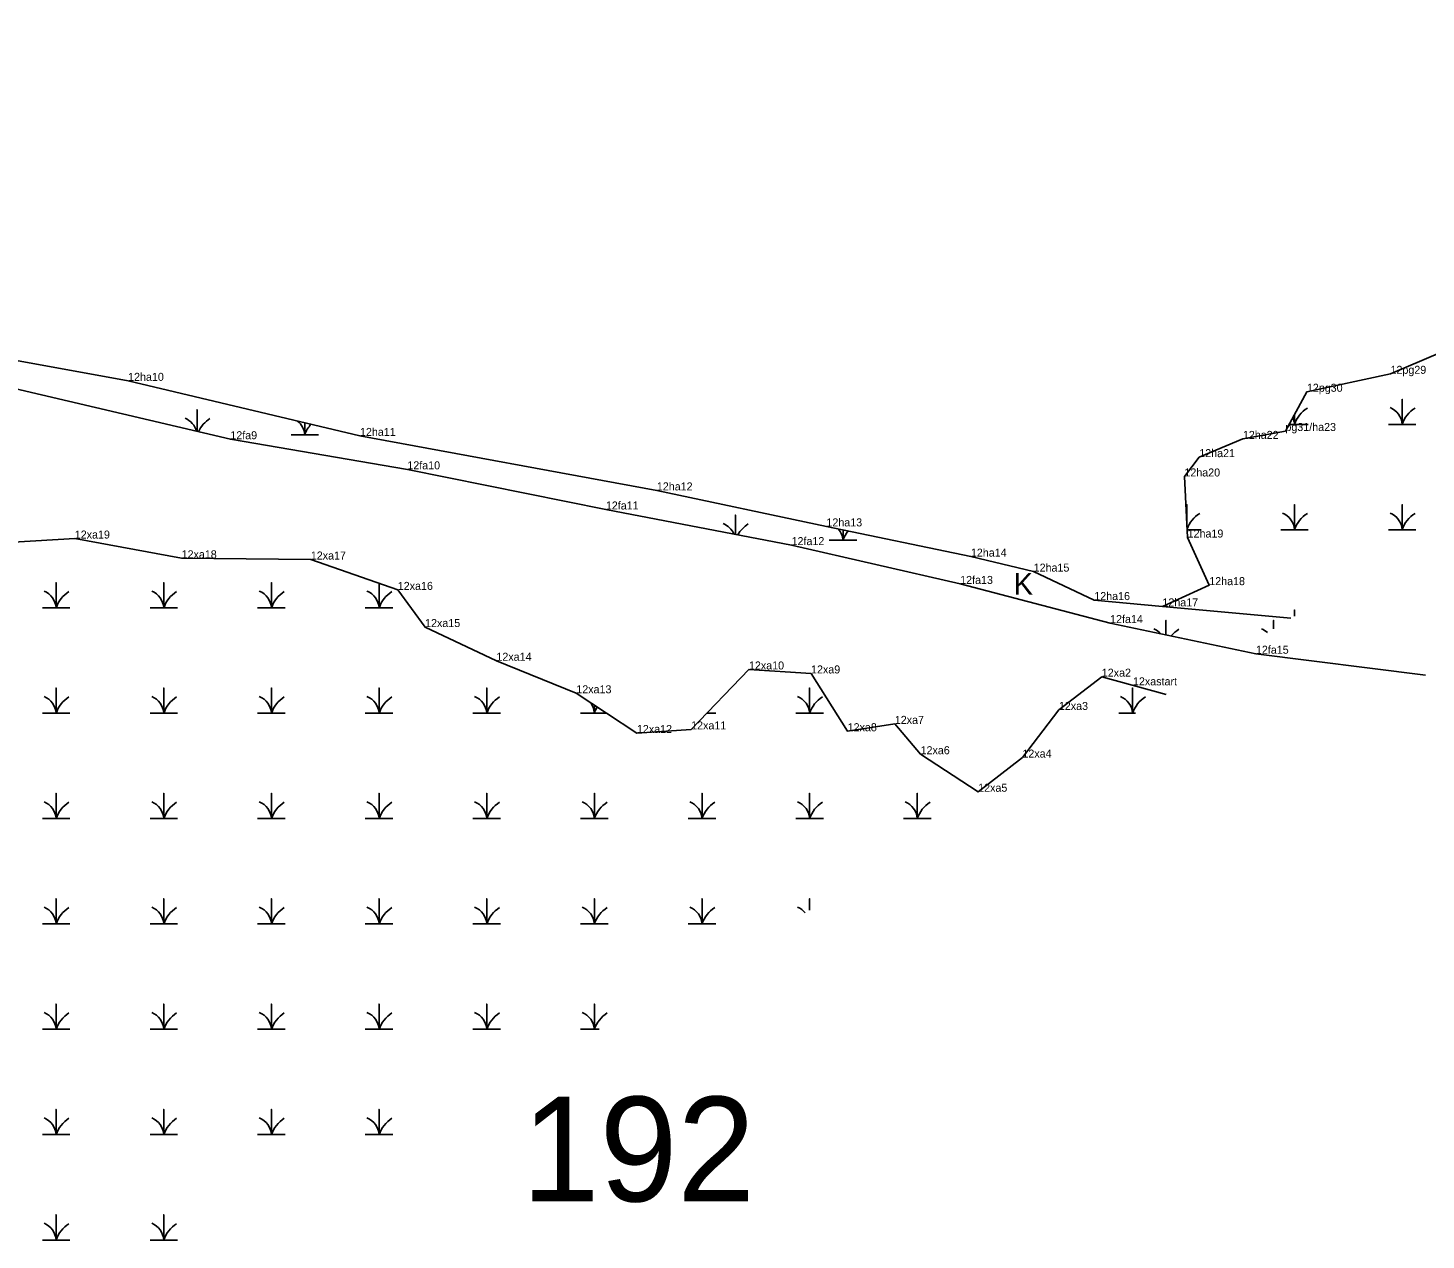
# Model space of a CAD drawing. Extents: x 2072529 to 2268796, y 436423 to 470397.
# Drawn here: x 2227708 to 2228581, y 449868 to 450625 of the extents above; entities that cross this region are included whole.
import ezdxf

# ---------------------------------------------------------------- set-up
doc = ezdxf.new("R2010")
doc.units = 0
for name, color, linetype in [('Default', 7, 'Continuous'), ('Exist Environmental Wetland Boundary', 7, 'Continuous'), ('Exist Environmental Wetland Boundary Cogo Comment', 7, 'Continuous'), ('Exist Environmental Wetland Boundary Cogo Point CELL', 7, 'Continuous'), ('Exist Hydro Swamp or Marsh', 7, 'Continuous')]:
    doc.layers.add(name, color=color, linetype=linetype)

msp = doc.modelspace()

# ---------------------------------------------------------------- linework, layer by layer
at = {"layer": 'Exist Environmental Wetland Boundary'}
msp.add_line((2228416.25, 450264.16), (2228496.47, 450256.71), dxfattribs=at)
for points in [[(2226888, 450625.39), (2226939.13, 450610.14), (2226984.32, 450594.17), (2227058.56, 450564.3), (2227157.52, 450534.56), (2227250.98, 450508.84), (2227383.88, 450477.24), (2227518.96, 450453.03), (2227616.6, 450432.85), (2227770.09, 450405.01), (2227914.95, 450370.61), (2228100.41, 450336.6), (2228206.35, 450314.11), (2228296.59, 450295.23), (2228335.8, 450285.87), (2228373.68, 450268.11), (2228416.25, 450264.16)], [(2228580.63, 450221.11), (2228474.67, 450234.59), (2228383.56, 450253.74), (2228289.9, 450278.18), (2228184.57, 450302.42), (2228068.56, 450324.67), (2227944.54, 450349.74), (2227833.96, 450368.55), (2227682.09, 450404.19), (2227531.66, 450431.23), (2227427.05, 450456.54), (2227285.93, 450486.54), (2227204.01, 450505.24), (2227068.94, 450546.01), (2226965.91, 450582.65), (2226856.88, 450620.93)], [(2228416.25, 450264.16), (2228445.5, 450277.43), (2228432, 450307.16), (2228429.98, 450345.29), (2228439.25, 450357.37), (2228466.52, 450368.75), (2228493.08, 450373.69), (2228506.5, 450398.2), (2228558.73, 450409.4), (2228600.72, 450427.39)], [(2227656.38, 450301.82), (2227736.78, 450306.52), (2227803.52, 450294.18), (2227884.23, 450293.43), (2227938.56, 450274.46), (2227955.62, 450251.26), (2228000.17, 450230.21), (2228050.09, 450209.88), (2228087.95, 450185.09), (2228121.83, 450187.32), (2228157.94, 450224.77), (2228196.73, 450222.29), (2228219.6, 450186.21), (2228249.06, 450190.79), (2228265.17, 450171.83), (2228301.14, 450148.4), (2228328.78, 450169.74), (2228351.55, 450199.49), (2228378.37, 450220.25), (2228418.57, 450209.1)]]:
    msp.add_lwpolyline(points, dxfattribs=at)
at = {"layer": 'Exist Environmental Wetland Boundary Cogo Point CELL'}
for p, q in [((2228558.73, 450409.4), (2228558.73, 450409.4)), ((2227770.09, 450405.01), (2227770.09, 450405.01)), ((2228506.5, 450398.2), (2228506.5, 450398.2)), ((2228493.08, 450373.69), (2228493.08, 450373.69)), ((2227833.96, 450368.55), (2227833.96, 450368.55)), ((2227914.95, 450370.61), (2227914.95, 450370.61)), ((2228466.52, 450368.75), (2228466.52, 450368.75)), ((2228439.25, 450357.37), (2228439.25, 450357.37)), ((2227944.54, 450349.74), (2227944.54, 450349.74)), ((2228429.98, 450345.29), (2228429.98, 450345.29)), ((2228100.41, 450336.6), (2228100.41, 450336.6)), ((2228068.56, 450324.67), (2228068.56, 450324.67)), ((2228206.35, 450314.11), (2228206.35, 450314.11)), ((2227736.78, 450306.52), (2227736.78, 450306.52)), ((2228184.57, 450302.42), (2228184.57, 450302.42)), ((2228432, 450307.16), (2228432, 450307.16)), ((2227803.52, 450294.18), (2227803.52, 450294.18)), ((2227884.23, 450293.43), (2227884.23, 450293.43)), ((2228296.59, 450295.23), (2228296.59, 450295.23)), ((2228335.8, 450285.87), (2228335.8, 450285.87)), ((2228289.9, 450278.18), (2228289.9, 450278.18)), ((2228445.5, 450277.43), (2228445.5, 450277.43)), ((2227938.56, 450274.46), (2227938.56, 450274.46)), ((2228373.68, 450268.11), (2228373.68, 450268.11)), ((2228416.25, 450264.16), (2228416.25, 450264.16)), ((2227955.62, 450251.26), (2227955.62, 450251.26)), ((2228383.56, 450253.74), (2228383.56, 450253.74)), ((2228474.67, 450234.59), (2228474.67, 450234.59)), ((2228000.17, 450230.21), (2228000.17, 450230.21)), ((2228157.94, 450224.77), (2228157.94, 450224.77)), ((2228196.73, 450222.29), (2228196.73, 450222.29)), ((2228378.37, 450220.25), (2228378.37, 450220.25)), ((2228397.85, 450214.84), (2228397.85, 450214.84)), ((2228580.63, 450221.11), (2228580.63, 450221.11)), ((2228050.09, 450209.88), (2228050.09, 450209.88)), ((2228351.55, 450199.49), (2228351.55, 450199.49)), ((2228249.06, 450190.79), (2228249.06, 450190.79)), ((2228087.95, 450185.09), (2228087.95, 450185.09)), ((2228121.83, 450187.32), (2228121.83, 450187.32)), ((2228219.6, 450186.21), (2228219.6, 450186.21)), ((2228265.17, 450171.83), (2228265.17, 450171.83)), ((2228328.78, 450169.74), (2228328.78, 450169.74)), ((2228301.14, 450148.4), (2228301.14, 450148.4))]:
    msp.add_line(p, q, dxfattribs=at)
at = {"layer": 'Exist Hydro Swamp or Marsh'}
for points in [[(2228557.44, 450377.79), (2228566.04, 450377.79), (2228566.04, 450393.57), (2228566.04, 450377.79), (2228574.64, 450377.79)], [(2227813.21, 450373.42), (2227813.21, 450387.01), (2227813.21, 450373.42)], [(2228495.32, 450377.79), (2228498.79, 450377.79), (2228498.79, 450384.12)], [(2228498.79, 450384.12), (2228498.79, 450377.79), (2228507.39, 450377.79)], [(2227871.86, 450371.23), (2227880.46, 450371.23), (2227880.46, 450378.8)], [(2227880.46, 450378.8), (2227880.46, 450371.23), (2227889.07, 450371.23)], [(2228431.54, 450315.86), (2228431.54, 450327.77), (2228431.54, 450315.86)], [(2228490.19, 450311.99), (2228498.79, 450311.99), (2228498.79, 450327.77), (2228498.79, 450311.99), (2228507.39, 450311.99)], [(2228557.44, 450311.99), (2228566.04, 450311.99), (2228566.04, 450327.77), (2228566.04, 450311.99), (2228574.64, 450311.99)], [(2228149.46, 450309.15), (2228149.46, 450321.21), (2228149.46, 450309.15)], [(2228208.11, 450305.43), (2228216.71, 450305.43), (2228216.71, 450311.94)], [(2228216.71, 450311.94), (2228216.71, 450305.43), (2228225.32, 450305.43)], [(2228431.75, 450311.99), (2228440.14, 450311.99)], [(2227716.52, 450263.25), (2227725.12, 450263.25), (2227725.12, 450279.03), (2227725.12, 450263.25), (2227733.72, 450263.25)], [(2227783.77, 450263.25), (2227792.37, 450263.25), (2227792.37, 450279.03), (2227792.37, 450263.25), (2227800.97, 450263.25)], [(2227851.02, 450263.25), (2227859.62, 450263.25), (2227859.62, 450279.03), (2227859.62, 450263.25), (2227868.22, 450263.25)], [(2227918.27, 450263.25), (2227926.87, 450263.25), (2227926.87, 450278.54)], [(2227926.87, 450278.54), (2227926.87, 450263.25), (2227935.47, 450263.25)], [(2228498.79, 450258.12), (2228498.79, 450261.97), (2228498.79, 450258.12)], [(2228418.46, 450246.4), (2228418.46, 450255.41), (2228418.46, 450246.4)], [(2228485.71, 450250.13), (2228485.71, 450255.41), (2228485.71, 450250.13)], [(2227716.52, 450197.45), (2227725.12, 450197.45), (2227725.12, 450213.23), (2227725.12, 450197.45), (2227733.72, 450197.45)], [(2227783.77, 450197.45), (2227792.37, 450197.45), (2227792.37, 450213.23), (2227792.37, 450197.45), (2227800.97, 450197.45)], [(2227851.02, 450197.45), (2227859.62, 450197.45), (2227859.62, 450213.23), (2227859.62, 450197.45), (2227868.22, 450197.45)], [(2227918.27, 450197.45), (2227926.87, 450197.45), (2227926.87, 450213.23), (2227926.87, 450197.45), (2227935.47, 450197.45)], [(2227985.52, 450197.45), (2227994.12, 450197.45), (2227994.12, 450213.23), (2227994.12, 450197.45), (2228002.72, 450197.45)], [(2228187.27, 450197.45), (2228195.87, 450197.45), (2228195.87, 450213.23), (2228195.87, 450197.45), (2228204.47, 450197.45)], [(2228389.02, 450197.45), (2228397.62, 450197.45), (2228397.62, 450213.23), (2228397.62, 450197.45), (2228399.5, 450197.45)], [(2228052.77, 450197.45), (2228061.37, 450197.45), (2228061.37, 450202.49)], [(2228061.37, 450202.49), (2228061.37, 450197.45), (2228069.07, 450197.45)], [(2228131.6, 450197.45), (2228137.22, 450197.45)], [(2227716.52, 450131.65), (2227725.12, 450131.65), (2227725.12, 450147.43), (2227725.12, 450131.65), (2227733.72, 450131.65)], [(2227783.77, 450131.65), (2227792.37, 450131.65), (2227792.37, 450147.43), (2227792.37, 450131.65), (2227800.97, 450131.65)], [(2227851.02, 450131.65), (2227859.62, 450131.65), (2227859.62, 450147.43), (2227859.62, 450131.65), (2227868.22, 450131.65)], [(2227918.27, 450131.65), (2227926.87, 450131.65), (2227926.87, 450147.43), (2227926.87, 450131.65), (2227935.47, 450131.65)], [(2227985.52, 450131.65), (2227994.12, 450131.65), (2227994.12, 450147.43), (2227994.12, 450131.65), (2228002.72, 450131.65)], [(2228052.77, 450131.65), (2228061.37, 450131.65), (2228061.37, 450147.43), (2228061.37, 450131.65), (2228069.97, 450131.65)], [(2228120.02, 450131.65), (2228128.62, 450131.65), (2228128.62, 450147.43), (2228128.62, 450131.65), (2228137.22, 450131.65)], [(2228187.27, 450131.65), (2228195.87, 450131.65), (2228195.87, 450147.43), (2228195.87, 450131.65), (2228204.47, 450131.65)], [(2228254.52, 450131.65), (2228263.12, 450131.65), (2228263.12, 450147.43), (2228263.12, 450131.65), (2228271.72, 450131.65)], [(2227716.52, 450065.85), (2227725.12, 450065.85), (2227725.12, 450081.63), (2227725.12, 450065.85), (2227733.72, 450065.85)], [(2227783.77, 450065.85), (2227792.37, 450065.85), (2227792.37, 450081.63), (2227792.37, 450065.85), (2227800.97, 450065.85)], [(2227851.02, 450065.85), (2227859.62, 450065.85), (2227859.62, 450081.63), (2227859.62, 450065.85), (2227868.22, 450065.85)], [(2227918.27, 450065.85), (2227926.87, 450065.85), (2227926.87, 450081.63), (2227926.87, 450065.85), (2227935.47, 450065.85)], [(2227985.52, 450065.85), (2227994.12, 450065.85), (2227994.12, 450081.63), (2227994.12, 450065.85), (2228002.72, 450065.85)], [(2228052.77, 450065.85), (2228061.37, 450065.85), (2228061.37, 450081.63), (2228061.37, 450065.85), (2228069.97, 450065.85)], [(2228120.02, 450065.85), (2228128.62, 450065.85), (2228128.62, 450081.63), (2228128.62, 450065.85), (2228137.22, 450065.85)], [(2228195.87, 450074.42), (2228195.87, 450081.63), (2228195.87, 450074.42)], [(2227716.52, 450000.05), (2227725.12, 450000.05), (2227725.12, 450015.83), (2227725.12, 450000.05), (2227733.72, 450000.05)], [(2227783.77, 450000.05), (2227792.37, 450000.05), (2227792.37, 450015.83), (2227792.37, 450000.05), (2227800.97, 450000.05)], [(2227851.02, 450000.05), (2227859.62, 450000.05), (2227859.62, 450015.83), (2227859.62, 450000.05), (2227868.22, 450000.05)], [(2227918.27, 450000.05), (2227926.87, 450000.05), (2227926.87, 450015.83), (2227926.87, 450000.05), (2227935.47, 450000.05)], [(2227985.52, 450000.05), (2227994.12, 450000.05), (2227994.12, 450015.83), (2227994.12, 450000.05), (2228002.72, 450000.05)], [(2228052.77, 450000.05), (2228061.37, 450000.05), (2228061.37, 450015.83), (2228061.37, 450000.05), (2228064.46, 450000.05)], [(2227716.52, 449934.25), (2227725.12, 449934.25), (2227725.12, 449950.03), (2227725.12, 449934.25), (2227733.72, 449934.25)], [(2227783.77, 449934.25), (2227792.37, 449934.25), (2227792.37, 449950.03), (2227792.37, 449934.25), (2227800.97, 449934.25)], [(2227851.02, 449934.25), (2227859.62, 449934.25), (2227859.62, 449950.03), (2227859.62, 449934.25), (2227868.22, 449934.25)], [(2227918.27, 449934.25), (2227926.87, 449934.25), (2227926.87, 449950.03), (2227926.87, 449934.25), (2227935.47, 449934.25)], [(2227716.52, 449868.45), (2227725.12, 449868.45), (2227725.12, 449884.23), (2227725.12, 449868.45), (2227733.72, 449868.45)], [(2227783.77, 449868.45), (2227792.37, 449868.45), (2227792.37, 449884.23), (2227792.37, 449868.45), (2227800.97, 449868.45)]]:
    msp.add_lwpolyline(points, dxfattribs=at)
for centre, radius, start, end in [((2227800.95, 450370.34), 12.3, 14.93161, 67.53497), ((2227831.46, 450365.17), 19.22, 122.12745, 155.19214), ((2228486.52, 450376.9), 12.3, 4.14034, 24.93697), ((2228517.03, 450371.73), 19.22, 122.12745, 161.62219), ((2228553.77, 450376.9), 12.3, 4.14034, 67.53497), ((2228584.28, 450371.73), 19.22, 122.12745, 161.62219), ((2227868.2, 450370.34), 12.3, 4.14034, 50.81137), ((2227898.71, 450365.17), 19.22, 138.54347, 161.62219), ((2228449.78, 450305.93), 19.22, 122.12745, 160.0063), ((2228486.52, 450311.1), 12.3, 4.14034, 67.53497), ((2228517.03, 450305.93), 19.22, 122.12745, 161.62219), ((2228553.77, 450311.1), 12.3, 4.14034, 67.53497), ((2228584.28, 450305.93), 19.22, 122.12745, 161.62219), ((2228137.2, 450304.54), 12.3, 22.93407, 67.53497), ((2228167.71, 450299.37), 19.22, 122.12745, 150.41007), ((2228204.45, 450304.54), 12.3, 4.14034, 40.686), ((2228234.96, 450299.37), 19.22, 141.69727, 161.62219), ((2227712.86, 450262.36), 12.3, 4.14034, 67.53497), ((2227743.36, 450257.19), 19.22, 122.12745, 161.62219), ((2227780.11, 450262.36), 12.3, 4.14034, 67.53497), ((2227810.61, 450257.19), 19.22, 122.12745, 161.62219), ((2227847.36, 450262.36), 12.3, 4.14034, 67.53497), ((2227877.86, 450257.19), 19.22, 122.12745, 161.62219), ((2227914.61, 450262.36), 12.3, 4.14034, 67.53497), ((2227945.11, 450257.19), 19.22, 122.12745, 161.62219), ((2228406.2, 450238.74), 12.3, 42.71799, 67.53497), ((2228436.71, 450233.57), 19.22, 122.12745, 140.85091), ((2228473.45, 450238.74), 12.3, 47.11509, 67.53497), ((2227712.86, 450196.56), 12.3, 4.14034, 67.53497), ((2227743.36, 450191.39), 19.22, 122.12745, 161.62219), ((2227780.11, 450196.56), 12.3, 4.14034, 67.53497), ((2227810.61, 450191.39), 19.22, 122.12745, 161.62219), ((2227847.36, 450196.56), 12.3, 4.14034, 67.53497), ((2227877.86, 450191.39), 19.22, 122.12745, 161.62219), ((2227914.61, 450196.56), 12.3, 4.14034, 67.53497), ((2227945.11, 450191.39), 19.22, 122.12745, 161.62219), ((2227981.86, 450196.56), 12.3, 4.14034, 67.53497), ((2228012.36, 450191.39), 19.22, 122.12745, 161.62219), ((2228183.61, 450196.56), 12.3, 4.14034, 67.53497), ((2228214.11, 450191.39), 19.22, 122.12745, 161.62219), ((2228385.36, 450196.56), 12.3, 4.14034, 67.53497), ((2228415.86, 450191.39), 19.22, 122.12745, 161.62219), ((2228049.11, 450196.56), 12.3, 4.14034, 38.52627), ((2228079.61, 450191.39), 19.22, 148.88911, 161.62219), ((2227712.86, 450130.76), 12.3, 4.14034, 67.53497), ((2227743.36, 450125.59), 19.22, 122.12745, 161.62219), ((2227780.11, 450130.76), 12.3, 4.14034, 67.53497), ((2227810.61, 450125.59), 19.22, 122.12745, 161.62219), ((2227847.36, 450130.76), 12.3, 4.14034, 67.53497), ((2227877.86, 450125.59), 19.22, 122.12745, 161.62219), ((2227914.61, 450130.76), 12.3, 4.14034, 67.53497), ((2227945.11, 450125.59), 19.22, 122.12745, 161.62219), ((2227981.86, 450130.76), 12.3, 4.14034, 67.53497), ((2228012.36, 450125.59), 19.22, 122.12745, 161.62219), ((2228049.11, 450130.76), 12.3, 4.14034, 67.53497), ((2228079.61, 450125.59), 19.22, 122.12745, 161.62219), ((2228116.36, 450130.76), 12.3, 4.14034, 67.53497), ((2228146.86, 450125.59), 19.22, 122.12745, 161.62219), ((2228183.61, 450130.76), 12.3, 4.14034, 67.53497), ((2228214.11, 450125.59), 19.22, 122.12745, 161.62219), ((2228250.86, 450130.76), 12.3, 4.14034, 67.53497), ((2228281.36, 450125.59), 19.22, 122.12745, 161.62219), ((2227712.86, 450064.96), 12.3, 4.14034, 67.53497), ((2227743.36, 450059.79), 19.22, 122.12745, 161.62219), ((2227780.11, 450064.96), 12.3, 4.14034, 67.53497), ((2227810.61, 450059.79), 19.22, 122.12745, 161.62219), ((2227847.36, 450064.96), 12.3, 4.14034, 67.53497), ((2227877.86, 450059.79), 19.22, 122.12745, 161.62219), ((2227914.61, 450064.96), 12.3, 4.14034, 67.53497), ((2227945.11, 450059.79), 19.22, 122.12745, 161.62219), ((2227981.86, 450064.96), 12.3, 4.14034, 67.53497), ((2228012.36, 450059.79), 19.22, 122.12745, 161.62219), ((2228049.11, 450064.96), 12.3, 4.14034, 67.53497), ((2228079.61, 450059.79), 19.22, 122.12745, 161.62219), ((2228116.36, 450064.96), 12.3, 4.14034, 67.53497), ((2228146.86, 450059.79), 19.22, 122.12745, 161.62219), ((2228183.61, 450064.96), 12.3, 39.52246, 67.53497), ((2227712.86, 449999.16), 12.3, 4.14034, 67.53497), ((2227743.36, 449993.99), 19.22, 122.12745, 161.62219), ((2227780.11, 449999.16), 12.3, 4.14034, 67.53497), ((2227810.61, 449993.99), 19.22, 122.12745, 161.62219), ((2227847.36, 449999.16), 12.3, 4.14034, 67.53497), ((2227877.86, 449993.99), 19.22, 122.12745, 161.62219), ((2227914.61, 449999.16), 12.3, 4.14034, 67.53497), ((2227945.11, 449993.99), 19.22, 122.12745, 161.62219), ((2227981.86, 449999.16), 12.3, 4.14034, 67.53497), ((2228012.36, 449993.99), 19.22, 122.12745, 161.62219), ((2228049.11, 449999.16), 12.3, 4.14034, 67.53497), ((2228079.61, 449993.99), 19.22, 122.12745, 161.62219), ((2227712.86, 449933.36), 12.3, 4.14034, 67.53497), ((2227743.36, 449928.19), 19.22, 122.12745, 161.62219), ((2227780.11, 449933.36), 12.3, 4.14034, 67.53497), ((2227810.61, 449928.19), 19.22, 122.12745, 161.62219), ((2227847.36, 449933.36), 12.3, 4.14034, 67.53497), ((2227877.86, 449928.19), 19.22, 122.12745, 161.62219), ((2227914.61, 449933.36), 12.3, 4.14034, 67.53497), ((2227945.11, 449928.19), 19.22, 122.12745, 161.62219), ((2227712.86, 449867.56), 12.3, 4.14034, 67.53497), ((2227743.36, 449862.39), 19.22, 122.12745, 161.62219), ((2227780.11, 449867.56), 12.3, 4.14034, 67.53497), ((2227810.61, 449862.39), 19.22, 122.12745, 161.62219)]:
    msp.add_arc(centre, radius, start, end, dxfattribs=at)

# ---------------------------------------------------------------- texts
at = {"layer": 'Default'}
msp.add_text('192', height=65.34, dxfattribs=at).set_placement((2228016.06, 449892.6))
at = {"layer": 'Exist Environmental Wetland Boundary Cogo Comment'}
for s, p in [('12ha10', (2227770.09, 450405.01)), ('12pg29', (2228558.73, 450409.4)), ('12pg30', (2228506.5, 450398.2)), ('12fa9', (2227833.96, 450368.55)), ('12ha11', (2227914.95, 450370.61)), ('12ha22', (2228466.52, 450368.75)), ('pg31/ha23', (2228493.08, 450373.69)), ('12ha21', (2228439.25, 450357.37)), ('12fa10', (2227944.54, 450349.74)), ('12ha20', (2228429.98, 450345.29)), ('12ha12', (2228100.41, 450336.6)), ('12fa11', (2228068.56, 450324.67)), ('12ha13', (2228206.35, 450314.11)), ('12xa19', (2227736.78, 450306.52)), ('12ha19', (2228432, 450307.16)), ('12fa12', (2228184.57, 450302.42)), ('12xa18', (2227803.52, 450294.18)), ('12xa17', (2227884.23, 450293.43)), ('12ha14', (2228296.59, 450295.23)), ('12ha15', (2228335.8, 450285.87)), ('12xa16', (2227938.56, 450274.46)), ('12fa13', (2228289.9, 450278.18)), ('12ha18', (2228445.5, 450277.43)), ('12ha16', (2228373.68, 450268.11)), ('12ha17', (2228416.25, 450264.16)), ('12fa14', (2228383.56, 450253.74)), ('12xa15', (2227955.62, 450251.26)), ('12xa14', (2228000.17, 450230.21)), ('12fa15', (2228474.67, 450234.59)), ('12xa10', (2228157.94, 450224.77)), ('12xa9', (2228196.73, 450222.29)), ('12xa2', (2228378.37, 450220.25)), ('12xa13', (2228050.09, 450209.88)), ('12xastart', (2228397.85, 450214.84)), ('12xa3', (2228351.55, 450199.49)), ('12xa12', (2228087.95, 450185.09)), ('12xa11', (2228121.83, 450187.32)), ('12xa8', (2228219.6, 450186.21)), ('12xa7', (2228249.06, 450190.79)), ('12xa6', (2228265.17, 450171.83)), ('12xa4', (2228328.78, 450169.74)), ('12xa5', (2228301.14, 450148.4))]:
    msp.add_text(s, height=5, dxfattribs=at).set_placement(p)
at = {"layer": 'Exist Hydro Swamp or Marsh'}
msp.add_text('K', height=13.6, dxfattribs=at).set_placement((2228323.29, 450271.44))

doc.saveas('drawing.dxf')
